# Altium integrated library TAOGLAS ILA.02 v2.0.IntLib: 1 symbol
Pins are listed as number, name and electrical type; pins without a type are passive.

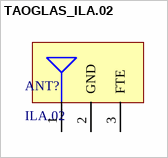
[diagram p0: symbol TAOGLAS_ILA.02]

## TAOGLAS_ILA.02
designator ANT?, comment ILA.02
Low Profile and High Efficient 868 MHz ISM Band Loop Antenna; ComponentLibStatus: Created; MFG: Taoglas; Temp_High: +85C; Temp_Low: -40C
footprint TAOGLAS_ILA.02 (Low Profile and High Efficient 868 MHz ISM Band Loop Antenna)
pins: 1 RF OUT, 2 GND, 3 FTE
